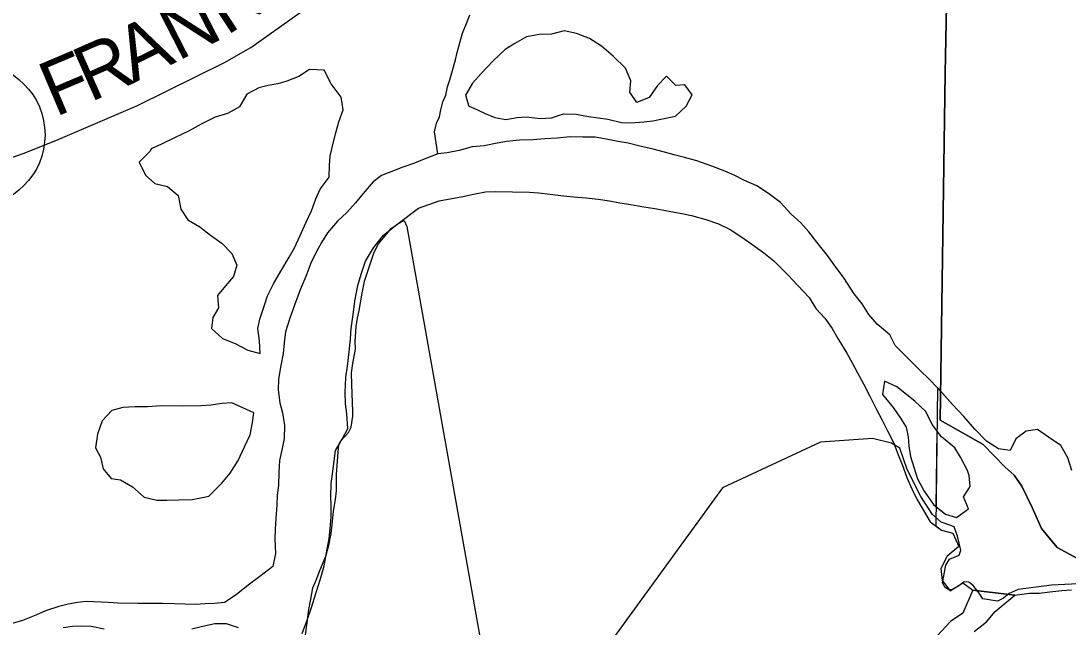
# Model space of a CAD drawing. Extents: x 0 to 34, y 0 to 22.
# Drawn here: x 7.278 to 8.362, y 19.138 to 19.765 of the extents above; entities that cross this region are included whole.
import ezdxf

# ---------------------------------------------------------------- set-up
doc = ezdxf.new("R2010")
doc.units = 0
for name, color, linetype in [('GM_X_Corporation', 7, 'Continuous'), ('GM_X_County_Road', 7, 'Continuous'), ('GM_X_County_Road_Text', 7, 'Continuous'), ('GM_X_Major_River', 7, 'Continuous'), ('GM_X_Minor_River', 7, 'Continuous'), ('GM_X_Unincorporated', 7, 'Continuous')]:
    doc.layers.add(name, color=color, linetype=linetype)

msp = doc.modelspace()

# ---------------------------------------------------------------- linework, layer by layer
at = {"layer": 'GM_X_Corporation'}
for points in [[(8.2412, 20.0451), (8.2346, 19.7113), (8.2293, 19.3521), (8.274, 19.3267), (8.2967, 19.3032), (8.3059, 19.2949), (8.3138, 19.2837), (8.3245, 19.2617), (8.3344, 19.2397), (8.3504, 19.2202), (8.3709, 19.2089), (8.3996, 19.2072), (8.461, 19.2162), (8.5053, 19.2254), (8.5711, 19.2518), (8.648, 19.2941), (8.73, 19.3298), (8.8288, 19.3684), (8.9, 19.3874), (8.9, 20.898)], [(8.9, 14.098), (8.9, 19.3874), (8.8288, 19.3684), (8.73, 19.3298), (8.648, 19.2941), (8.5711, 19.2518), (8.5053, 19.2254), (8.461, 19.2162), (8.3996, 19.2072), (8.3709, 19.2089), (8.3504, 19.2202), (8.3344, 19.2397), (8.3245, 19.2617), (8.3138, 19.2837), (8.3059, 19.2949), (8.2967, 19.3032), (8.274, 19.3267), (8.2293, 19.3521), (8.2346, 19.7113), (8.2412, 20.0451)], [(7.5723, 19.1298), (7.5736, 19.1397), (7.5758, 19.1559), (7.578, 19.1665), (7.5801, 19.1782), (7.5833, 19.1864), (7.5873, 19.1962), (7.5933, 19.2112), (7.5966, 19.2221), (7.5991, 19.2346), (7.6001, 19.2436), (7.6015, 19.2576), (7.6033, 19.2697), (7.6046, 19.2788), (7.6046, 19.2958), (7.6062, 19.3189), (7.6068, 19.3264), (7.6087, 19.3302), (7.6169, 19.3391), (7.6197, 19.3447), (7.6214, 19.356), (7.6215, 19.361), (7.621, 19.3704), (7.6202, 19.389), (7.6201, 19.4008), (7.6215, 19.4106), (7.624, 19.4253), (7.6238, 19.4333), (7.6249, 19.4488), (7.6263, 19.4575), (7.6279, 19.4654), (7.631, 19.4835), (7.6335, 19.4959), (7.6367, 19.5053), (7.6388, 19.5125), (7.6436, 19.526), (7.648, 19.5346), (7.653, 19.5406), (7.6612, 19.5503), (7.6681, 19.5554), (7.6746, 19.5587), (7.6771, 19.5524), (7.7616, 19.0792)], [(8.4409, 19.186), (8.3446, 19.1811), (8.3101, 19.1765), (8.3009, 19.1725), (8.2951, 19.1677), (8.2886, 19.1644), (8.2735, 19.167), (8.2698, 19.1728), (8.2636, 19.1809), (8.2591, 19.1843), (8.2542, 19.1845), (8.2488, 19.1804), (8.2423, 19.1767), (8.2385, 19.1764), (8.2347, 19.1788), (8.2318, 19.1834), (8.2352, 19.2019), (8.2391, 19.2082), (8.249, 19.2122), (8.2507, 19.2175), (8.2475, 19.2319), (8.2439, 19.2415), (8.2394, 19.2431), (8.2304, 19.2463), (8.2215, 19.2544), (8.2094, 19.2728), (8.1951, 19.3008), (8.1876, 19.3229), (8.179, 19.328), (8.1594, 19.3329), (8.1056, 19.3291), (8.0039, 19.2819), (7.8648, 19.09)]]:
    msp.add_lwpolyline(points, dxfattribs=at)
at = {"layer": 'GM_X_County_Road'}
msp.add_lwpolyline([(7.2271, 19.6098), (7.2811, 19.6284), (7.3162, 19.6427), (7.3984, 19.6777), (7.4886, 19.7223), (7.5157, 19.7379), (7.5777, 19.7818), (7.6742, 19.8562), (7.7116, 19.8844), (7.7542, 19.9166), (7.7862, 19.9347), (7.8333, 19.9572), (7.8737, 19.9675), (7.91, 19.9746), (7.988, 19.9925), (8.0578, 20.005), (8.1281, 20.0204), (8.2142, 20.0385), (8.2414, 20.0445)], dxfattribs=at)
at = {"layer": 'GM_X_Major_River'}
for p, q in [((8.2265, 19.3857), (8.2248, 19.2426)), ((8.226, 19.341), (8.225, 19.2625)), ((8.2633, 19.1761), (8.3068, 19.1706))]:
    msp.add_line(p, q, dxfattribs=at)
for points in [[(8.3658, 19.2997), (8.3615, 19.313), (8.3542, 19.3257), (8.3415, 19.3343), (8.3303, 19.3422), (8.3185, 19.3405), (8.3077, 19.3327), (8.3018, 19.3207), (8.2897, 19.3221), (8.2773, 19.3303), (8.2654, 19.3427), (8.254, 19.3559), (8.2421, 19.3683), (8.231, 19.3807), (8.2195, 19.393), (8.2072, 19.4047), (8.1946, 19.4175), (8.1827, 19.4291), (8.1773, 19.4402), (8.1642, 19.4515), (8.1557, 19.4612), (8.1488, 19.4723), (8.1403, 19.4828), (8.1296, 19.4993), (8.1197, 19.5128), (8.1127, 19.5225), (8.1016, 19.5364), (8.0935, 19.5468), (8.085, 19.5564), (8.0753, 19.5654), (8.0642, 19.5774), (8.0515, 19.5868), (8.0395, 19.5946), (8.026, 19.6006), (8.0162, 19.6057), (8.0064, 19.6097), (7.9929, 19.6149), (7.9775, 19.6206), (7.9646, 19.6239), (7.9541, 19.6267), (7.9439, 19.6296), (7.9322, 19.6325), (7.9186, 19.6358), (7.9065, 19.6387), (7.894, 19.6409), (7.882, 19.6434), (7.8721, 19.6448), (7.8596, 19.645), (7.8463, 19.6453), (7.833, 19.644), (7.8201, 19.6432), (7.8076, 19.6423), (7.7939, 19.6418), (7.7806, 19.6406), (7.7707, 19.6389), (7.7573, 19.6361), (7.7448, 19.6348), (7.7314, 19.6313), (7.7189, 19.6289), (7.7093, 19.6276), (7.6971, 19.6229), (7.6852, 19.6182), (7.673, 19.6139)], [(7.673, 19.6139), (7.6512, 19.6054), (7.6425, 19.5987), (7.632, 19.5867), (7.6242, 19.577), (7.6153, 19.5669), (7.6056, 19.558), (7.5951, 19.546), (7.5889, 19.5359), (7.583, 19.5253), (7.5778, 19.5144), (7.5726, 19.5008), (7.567, 19.4869), (7.561, 19.471), (7.5562, 19.4574), (7.5517, 19.4434), (7.5504, 19.4321), (7.5494, 19.4211), (7.5468, 19.4086), (7.5443, 19.3945), (7.5441, 19.3835), (7.5457, 19.3698), (7.5485, 19.3595), (7.5505, 19.3465), (7.5502, 19.3328), (7.5481, 19.3226), (7.5456, 19.3101), (7.5446, 19.2976), (7.5443, 19.2843), (7.543, 19.2744), (7.5428, 19.2638), (7.5417, 19.2501), (7.5408, 19.2391), (7.5406, 19.2292), (7.5414, 19.214), (7.5384, 19.2004), (7.525, 19.19), (7.513, 19.1811), (7.5007, 19.1711), (7.4884, 19.1633), (7.4781, 19.162), (7.4686, 19.1618), (7.4584, 19.1612), (7.4364, 19.1617), (7.4243, 19.1623), (7.4095, 19.1622), (7.3989, 19.162), (7.378, 19.1624), (7.3685, 19.163), (7.3458, 19.1642), (7.3363, 19.1633), (7.3268, 19.1615), (7.3169, 19.1591), (7.3031, 19.1544), (7.2932, 19.15), (7.2794, 19.1446), (7.2661, 19.1407)], [(7.667, 19.5545), (7.6895, 19.5714), (7.6999, 19.5754), (7.7106, 19.5789), (7.7353, 19.5834), (7.7479, 19.5862), (7.7586, 19.5882), (7.7692, 19.5888), (7.8041, 19.588), (7.8136, 19.5875), (7.8257, 19.5861), (7.8393, 19.5843), (7.8499, 19.5833), (7.8628, 19.5823), (7.8753, 19.5809), (7.887, 19.5791), (7.8976, 19.577), (7.9093, 19.5752), (7.9206, 19.5731), (7.9362, 19.5709), (7.9467, 19.5688), (7.9603, 19.5662), (7.972, 19.5637), (7.9868, 19.5596), (7.9999, 19.5552), (8.0119, 19.5492), (8.0239, 19.5414), (8.0344, 19.5343), (8.0467, 19.5253), (8.0571, 19.5168), (8.072, 19.502), (8.0816, 19.4919), (8.0939, 19.4788), (8.1008, 19.4676), (8.1101, 19.4576), (8.1175, 19.4468), (8.1233, 19.4364), (8.1328, 19.4214), (8.1383, 19.4114), (8.1438, 19.401), (8.15, 19.3895), (8.1565, 19.3769), (8.1634, 19.363), (8.1693, 19.3519), (8.1747, 19.3408), (8.1813, 19.3281), (8.1859, 19.3159), (8.1899, 19.3059), (8.1949, 19.2925), (8.2, 19.281), (8.2054, 19.2703), (8.2109, 19.2607), (8.2189, 19.2468), (8.2309, 19.2382), (8.2426, 19.235), (8.2487, 19.2212), (8.2367, 19.2112), (8.23, 19.1984), (8.2316, 19.1858), (8.2398, 19.1754), (8.2528, 19.1835), (8.2633, 19.1761)], [(7.5689, 19.1309), (7.5745, 19.146), (7.5786, 19.1581), (7.583, 19.1725), (7.5879, 19.1876), (7.5916, 19.2012), (7.5941, 19.2145), (7.5967, 19.2296), (7.598, 19.2395), (7.599, 19.252), (7.5989, 19.2638), (7.5987, 19.2733), (7.599, 19.2862), (7.6003, 19.2965), (7.6017, 19.3071), (7.6035, 19.3204), (7.6102, 19.3324), (7.6161, 19.3433), (7.6152, 19.3585), (7.6139, 19.3688), (7.6134, 19.381), (7.6141, 19.3962), (7.6159, 19.408), (7.6177, 19.4228), (7.6191, 19.436), (7.6197, 19.447), (7.6219, 19.4637), (7.6233, 19.4751), (7.6267, 19.4914), (7.6299, 19.5031), (7.6344, 19.5167), (7.6426, 19.5303), (7.6531, 19.5434), (7.667, 19.5545)], [(8.1844, 19.3865), (8.1717, 19.3925), (8.1698, 19.3785), (8.1806, 19.365), (8.1875, 19.355), (8.1941, 19.3446), (8.1962, 19.3347), (8.1971, 19.3251), (8.1988, 19.3145), (8.202, 19.3034), (8.2059, 19.2912), (8.2128, 19.2785), (8.2224, 19.2646), (8.235, 19.2545), (8.2464, 19.2512), (8.2587, 19.2601), (8.2537, 19.2727), (8.2603, 19.2832), (8.2595, 19.2946)], [(8.2595, 19.2946), (8.2577, 19.3), (8.2504, 19.3138), (8.2445, 19.3234), (8.2307, 19.3347), (8.2211, 19.3474), (8.2146, 19.3609), (8.2031, 19.3717), (8.1844, 19.3865)], [(8.3658, 19.2997), (8.3615, 19.313), (8.3542, 19.3257), (8.3415, 19.3343), (8.3303, 19.3422), (8.3185, 19.3405), (8.3077, 19.3327), (8.3018, 19.3207), (8.2897, 19.3221), (8.2773, 19.3303), (8.2654, 19.3427), (8.254, 19.3559), (8.2421, 19.3683), (8.2265, 19.3857)], [(8.2595, 19.2946), (8.2577, 19.3), (8.2504, 19.3138), (8.2445, 19.3234), (8.2307, 19.3347), (8.226, 19.341)], [(8.225, 19.2625), (8.235, 19.2545), (8.2464, 19.2512), (8.2587, 19.2601), (8.2537, 19.2727), (8.2603, 19.2832), (8.2595, 19.2946)], [(8.2248, 19.2426), (8.2309, 19.2382), (8.2426, 19.235), (8.2487, 19.2212), (8.2367, 19.2112), (8.23, 19.1984), (8.2316, 19.1858), (8.2398, 19.1754), (8.2528, 19.1835), (8.2633, 19.1761)], [(8.3068, 19.1706), (8.322, 19.173), (8.3319, 19.1728), (8.3429, 19.1741), (8.3555, 19.1757), (8.3654, 19.1762)], [(7.3638, 19.1357), (7.3506, 19.1383), (7.3407, 19.1385), (7.3312, 19.1383), (7.3214, 19.1369)], [(7.503, 19.1368), (7.4906, 19.1412), (7.4785, 19.1411), (7.4644, 19.1379), (7.4548, 19.1355)]]:
    msp.add_lwpolyline(points, dxfattribs=at)
at = {"layer": 'GM_X_Minor_River'}
msp.add_line((8.3068, 19.1706), (8.2633, 19.1761), dxfattribs=at)
for points in [[(7.7093, 19.6276), (7.7059, 19.6504), (7.7079, 19.6595), (7.711, 19.6659), (7.7125, 19.6731), (7.7145, 19.6815), (7.7176, 19.6886), (7.7195, 19.697), (7.7218, 19.7045), (7.7277, 19.725), (7.7292, 19.7325), (7.7323, 19.7428), (7.735, 19.7526), (7.7389, 19.7628), (7.7424, 19.7715)], [(7.8854, 19.6635), (7.8994, 19.6601), (7.9093, 19.6599), (7.9226, 19.6608), (7.9321, 19.6618), (7.942, 19.6638), (7.9553, 19.6666), (7.9666, 19.677), (7.9725, 19.6887), (7.9651, 19.6991), (7.9556, 19.6985), (7.946, 19.7082), (7.9367, 19.6985), (7.9281, 19.6861), (7.9154, 19.6807), (7.9081, 19.6915), (7.9091, 19.7033), (7.9037, 19.7163), (7.891, 19.7287), (7.8788, 19.7392), (7.8664, 19.7471), (7.8529, 19.7523), (7.84, 19.7552), (7.827, 19.7517), (7.8141, 19.7512), (7.8012, 19.7488), (7.7889, 19.7418), (7.7789, 19.7356), (7.7665, 19.724), (7.7541, 19.711), (7.7451, 19.7009), (7.738, 19.6885), (7.7415, 19.6771)], [(7.4114, 19.6306), (7.4002, 19.6191), (7.4067, 19.6056), (7.4164, 19.5971), (7.4296, 19.5938), (7.4404, 19.5844), (7.4432, 19.5703), (7.4505, 19.5595), (7.4629, 19.552), (7.4741, 19.5434), (7.4857, 19.5352), (7.4961, 19.5244), (7.5012, 19.5125), (7.4979, 19.5008), (7.4894, 19.4911), (7.4812, 19.4809), (7.4824, 19.4684), (7.4765, 19.4582), (7.4752, 19.4468), (7.4863, 19.4364), (7.4995, 19.4315), (7.5127, 19.4244), (7.5255, 19.4211), (7.5246, 19.4341), (7.523, 19.4467), (7.5251, 19.4565), (7.5295, 19.4701), (7.5331, 19.4807), (7.5391, 19.4931), (7.5469, 19.5063), (7.5556, 19.5206), (7.5611, 19.5303), (7.5666, 19.5424), (7.573, 19.5571), (7.5785, 19.5688), (7.583, 19.5812), (7.5877, 19.591), (7.5967, 19.6034), (7.5973, 19.6159), (7.5979, 19.6254), (7.6004, 19.636), (7.6037, 19.6493), (7.607, 19.661), (7.6114, 19.6731), (7.6094, 19.6864), (7.599, 19.7003), (7.5917, 19.7142)], [(7.5766, 19.7149), (7.5654, 19.7078), (7.5532, 19.7028), (7.5437, 19.7003), (7.5338, 19.6986), (7.5242, 19.6961), (7.5116, 19.6895), (7.5041, 19.6763), (7.4915, 19.6694), (7.4789, 19.6658), (7.4643, 19.6585), (7.452, 19.6515), (7.4375, 19.6446), (7.4233, 19.6376), (7.4126, 19.6329), (7.4114, 19.6306)], [(7.5917, 19.7142), (7.5766, 19.7149)], [(7.7415, 19.6771), (7.7461, 19.6755), (7.7585, 19.6695), (7.7682, 19.6655), (7.7799, 19.6634), (7.7914, 19.6654), (7.8013, 19.666), (7.8153, 19.6642), (7.827, 19.6651), (7.8396, 19.669), (7.8525, 19.6687), (7.8654, 19.6662), (7.8854, 19.6635)], [(7.5189, 19.3597), (7.496, 19.37), (7.4861, 19.3691), (7.4743, 19.3674), (7.4645, 19.3668), (7.4455, 19.3664), (7.4231, 19.3669), (7.4087, 19.3656), (7.3958, 19.3659), (7.3833, 19.365), (7.3718, 19.3618), (7.3617, 19.3513), (7.3569, 19.3374), (7.3551, 19.3233), (7.3602, 19.3137), (7.363, 19.3015), (7.3711, 19.2915), (7.381, 19.2901), (7.3933, 19.283), (7.4053, 19.2722), (7.4185, 19.2692), (7.4287, 19.269), (7.4416, 19.2696), (7.4549, 19.2697), (7.4675, 19.2721)], [(7.4675, 19.2721), (7.4724, 19.2731), (7.4856, 19.2866), (7.4945, 19.297), (7.5028, 19.3102), (7.5091, 19.3245), (7.5151, 19.3369), (7.5176, 19.3494), (7.5189, 19.3597)], [(8.2633, 19.1761), (8.2529, 19.152), (8.2402, 19.1435), (8.2262, 19.1286)], [(8.2646, 19.1331), (8.2774, 19.1431), (8.2863, 19.1539), (8.3068, 19.1706)]]:
    msp.add_lwpolyline(points, dxfattribs=at)
at = {"layer": 'GM_X_Unincorporated'}
msp.add_circle((7.2283, 19.6474), 0.0744, dxfattribs=at)

# ---------------------------------------------------------------- texts
at = {"layer": 'GM_X_County_Road_Text'}
for s, rotation, p in [('K', 33.3997, (7.4905, 19.7494)), ('N', 27.1309, (7.4401, 19.7232)), ('A', 26.0618, (7.3941, 19.7007)), ('R', 23.822, (7.3493, 19.6808)), ('F', 23.0014, (7.3132, 19.6655))]:
    msp.add_text(s, height=0.0568, rotation=rotation, dxfattribs=at).set_placement(p)

doc.saveas('drawing.dxf')
